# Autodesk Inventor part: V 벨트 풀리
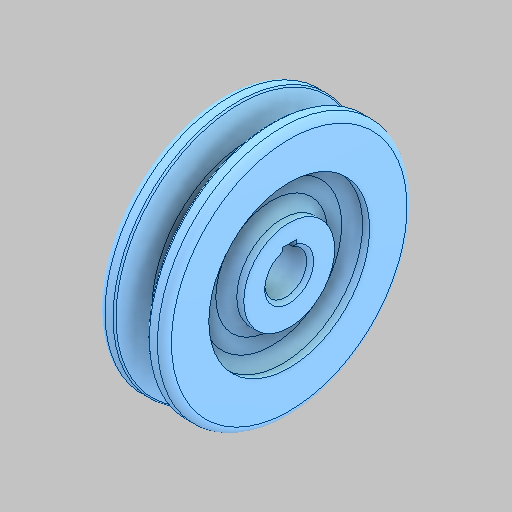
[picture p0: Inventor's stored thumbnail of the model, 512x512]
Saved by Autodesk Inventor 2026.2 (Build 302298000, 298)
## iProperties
Created: 2026-06
Part Number: V 벨트 풀리
Material: 강철, 주조
Document SubType Name: Modeling
Designer: sec7
Density: 7.85 g/cm^3
Appearance: 기본값
Author: jhkim
Sending System: Autodesk Inventor 2027
Preprocessor: ST-DEVELOPER v20.1
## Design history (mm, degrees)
feature "솔리드1"
node "솔리드2"
